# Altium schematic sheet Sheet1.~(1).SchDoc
size A; SheetNumber: 1; SheetTotal: 1
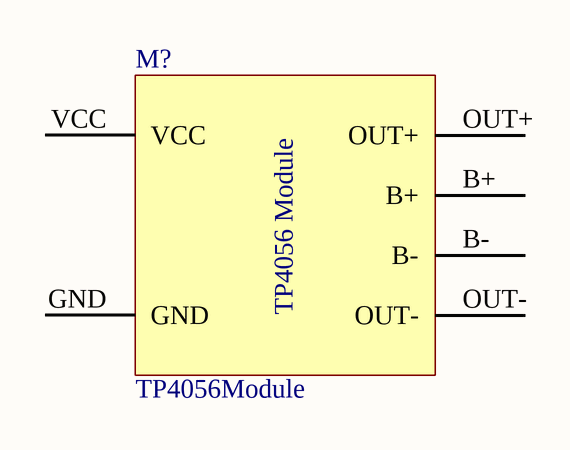
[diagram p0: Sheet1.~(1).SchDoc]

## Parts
M?  TP4056Module

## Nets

Not connected (* = marked no-connect by the designer): M? B+ B- GND OUT+ OUT- VCC

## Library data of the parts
M? = TP4056Module: TP4056 Module for managing battery charging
